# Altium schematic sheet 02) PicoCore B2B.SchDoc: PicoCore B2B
size A3; Origin: Eagle; DocumentNumber: 2; SheetNumber: 2; SheetTotal: 10
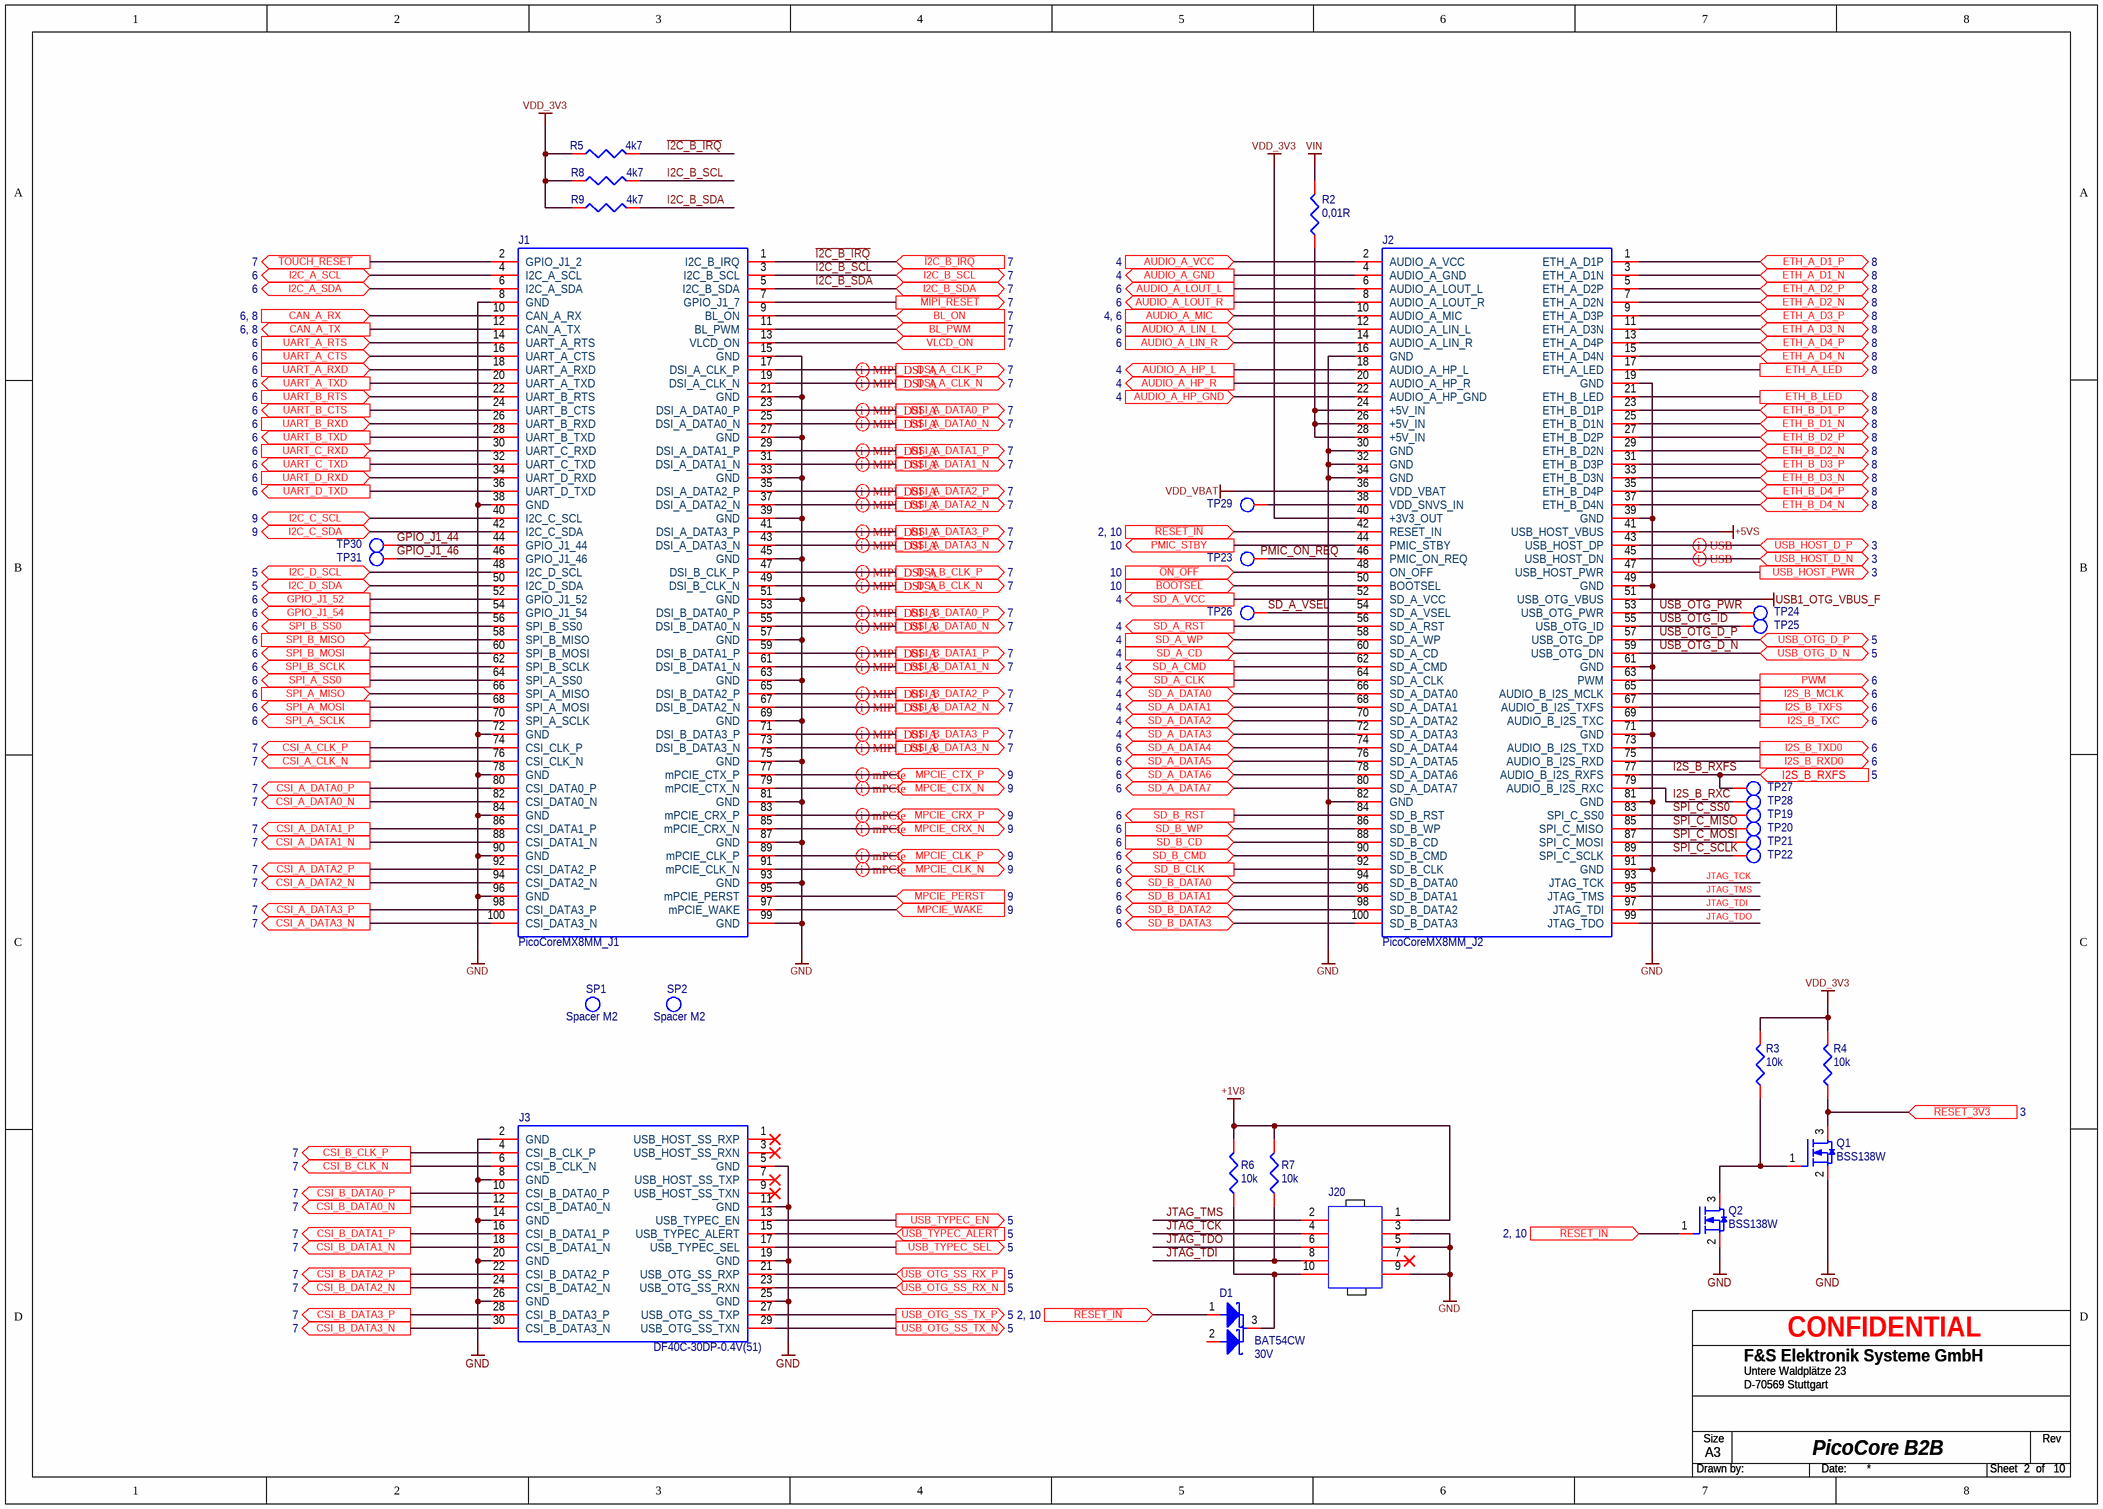
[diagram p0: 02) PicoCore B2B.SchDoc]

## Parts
D1  BAT54CW  Voltage: 30V  [SOT323 (SC70)]
J1  PicoCoreMX8MM_J1  [DF40C-100DS-0.4V(51)]
J2  PicoCoreMX8MM_J2  [DF40C-100DS-0.4V(51)]
J3  DF40C-30DP-0.4V(51)  [DF40C-30DS-0.4V(51)]
J20  (no value)  [J-B2B-5X2-127MM-WR-PHD]
Q1  BSS138W  [SOT323 (SC70)]
Q2  BSS138W  [SOT323 (SC70)]
R2  0,01R  [R0805]
R3  10k  [R0402]
R4  10k  [R0402]
R5  4k7  [R0402]
R6  10k  [R0402]
R7  10k  [R0402]
R8  4k7  [R0402]
R9  4k7  [R0402]
SP1  Spacer M2  [Spacer_M2]
SP2  Spacer M2  [Spacer_M2]
TP19  TESTPOINT  [TESTPOINT]  (value not drawn)  (mechanical)
TP20  TESTPOINT  [TESTPOINT]  (value not drawn)  (mechanical)
TP21  TESTPOINT  [TESTPOINT]  (value not drawn)  (mechanical)
TP22  TESTPOINT  [TESTPOINT]  (value not drawn)  (mechanical)
TP23  TESTPOINT  [TESTPOINT]  (value not drawn)  (mechanical)
TP24  TESTPOINT  [TESTPOINT]  (value not drawn)  (mechanical)
TP25  TESTPOINT  [TESTPOINT]  (value not drawn)  (mechanical)
TP26  TESTPOINT  [TESTPOINT]  (value not drawn)  (mechanical)
TP27  TESTPOINT  [TESTPOINT]  (value not drawn)  (mechanical)
TP28  TESTPOINT  [TESTPOINT]  (value not drawn)  (mechanical)
TP29  TESTPOINT  [TESTPOINT]  (value not drawn)  (mechanical)
TP30  TESTPOINT  [TESTPOINT]  (value not drawn)  (mechanical)
TP31  TESTPOINT  [TESTPOINT]  (value not drawn)  (mechanical)

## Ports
AUDIO_A_GND (out, see 4), AUDIO_A_HP_GND (in, see 4), AUDIO_A_HP_L (out, see 4), AUDIO_A_HP_R (out, see 4), AUDIO_A_LIN_L (in, see 6), AUDIO_A_LIN_R (in, see 6), AUDIO_A_LOUT_L (out, see 6), AUDIO_A_LOUT_R (out, see 6), AUDIO_A_MIC (in, see 4, 6), AUDIO_A_VCC (in, see 4), BL_ON (in, see 7), BL_PWM (in, see 7), CAN_A_RX (in, see 6, 8), CAN_A_TX (out, see 6, 8), CSI_A_CLK_N (out, see 7), CSI_A_CLK_P (out, see 7), CSI_A_DATA0_N (out, see 7), CSI_A_DATA0_P (out, see 7), CSI_A_DATA1_N (out, see 7), CSI_A_DATA1_P (out, see 7), CSI_A_DATA2_N (out, see 7), CSI_A_DATA2_P (out, see 7), CSI_A_DATA3_N (out, see 7), CSI_A_DATA3_P (out, see 7), CSI_B_CLK_N (out, see 7), CSI_B_CLK_P (out, see 7), CSI_B_DATA0_N (out, see 7), CSI_B_DATA0_P (out, see 7), CSI_B_DATA1_N (out, see 7), CSI_B_DATA1_P (out, see 7), CSI_B_DATA2_N (out, see 7), CSI_B_DATA2_P (out, see 7), CSI_B_DATA3_N (out, see 7), CSI_B_DATA3_P (out, see 7), DSI_A_CLK_N (out, see 7), DSI_A_CLK_P (out, see 7), DSI_A_DATA0_N (out, see 7), DSI_A_DATA0_P (out, see 7), DSI_A_DATA1_N (out, see 7), DSI_A_DATA1_P (out, see 7), DSI_A_DATA2_N (out, see 7), DSI_A_DATA2_P (out, see 7), DSI_A_DATA3_N (out, see 7), DSI_A_DATA3_P (out, see 7), DSI_B_CLK_N (out, see 7), DSI_B_CLK_P (out, see 7), DSI_B_DATA0_N (out, see 7), DSI_B_DATA0_P (out, see 7), DSI_B_DATA1_N (out, see 7), DSI_B_DATA1_P (out, see 7), DSI_B_DATA2_N (out, see 7), DSI_B_DATA2_P (out, see 7), DSI_B_DATA3_N (out, see 7), DSI_B_DATA3_P (out, see 7), ETH_A_D1_N (bidir, see 8), ETH_A_D1_P (bidir, see 8), ETH_A_D2_N (bidir, see 8), ETH_A_D2_P (bidir, see 8), ETH_A_D3_N (bidir, see 8), ETH_A_D3_P (bidir, see 8), ETH_A_D4_N (bidir, see 8), ETH_A_D4_P (bidir, see 8), ETH_A_LED (out, see 8), ETH_B_D1_N (bidir, see 8), ETH_B_D1_P (bidir, see 8), ETH_B_D2_N (bidir, see 8), ETH_B_D2_P (bidir, see 8), ETH_B_D3_N (bidir, see 8), ETH_B_D3_P (bidir, see 8), ETH_B_D4_N (bidir, see 8), ETH_B_D4_P (bidir, see 8), ETH_B_LED (out, see 8), GPIO_J1_52 (out, see 6), GPIO_J1_54 (out, see 6), I2C_A_SCL (bidir, see 6), I2C_A_SDA (bidir, see 6), I2C_B_SCL (bidir, see 7), I2C_B_SDA (bidir, see 7), I2C_C_SCL (bidir, see 9), I2C_C_SDA (bidir, see 9), I2C_D_SCL (bidir, see 5), I2C_D_SDA (bidir, see 5), I2S_B_MCLK (out, see 6), I2S_B_RXD0 (out, see 6), I2S_B_RXFS (in, see 5), I2S_B_TXC (out, see 6), I2S_B_TXD0 (out, see 6), I2S_B_TXFS (out, see 6), MPCIE_CLK_N (bidir, see 9), MPCIE_CLK_P (bidir, see 9), MPCIE_CRX_N (bidir, see 9), MPCIE_CRX_P (bidir, see 9), MPCIE_CTX_N (bidir, see 9), MPCIE_CTX_P (bidir, see 9), MPCIE_PERST (in, see 9), MPCIE_WAKE (in, see 9), PMIC_STBY (out, see 10), PWM (out, see 6), SD_A_CD (in, see 4), SD_A_CLK (out, see 4), SD_A_CMD (out, see 4), SD_A_DATA0 (bidir, see 4), SD_A_DATA1 (bidir, see 4), SD_A_DATA2 (bidir, see 4), SD_A_DATA3 (bidir, see 4), SD_A_DATA4 (bidir, see 6), SD_A_DATA5 (bidir, see 6), SD_A_DATA6 (bidir, see 6), SD_A_DATA7 (bidir, see 6), SD_A_RST (out, see 4), SD_A_VCC (out, see 4), SD_A_WP (in, see 4), SD_B_CD (in, see 6), SD_B_CLK (out, see 6), SD_B_CMD (bidir, see 6), SD_B_DATA0 (bidir, see 6), SD_B_DATA1 (bidir, see 6), SD_B_DATA2 (bidir, see 6), SD_B_DATA3 (bidir, see 6), SD_B_RST (out, see 6), SD_B_WP (in, see 6), SPI_A_MISO (in, see 6), SPI_A_MOSI (out, see 6), SPI_A_SCLK (out, see 6), SPI_A_SS0 (out, see 6), SPI_B_MISO (in, see 6), SPI_B_MOSI (out, see 6), SPI_B_SCLK (out, see 6), SPI_B_SS0 (out, see 6), UART_A_CTS (in, see 6), UART_A_RTS (in, see 6), UART_A_RXD (in, see 6), UART_A_TXD (out, see 6), UART_B_CTS (out, see 6), UART_B_RTS (in, see 6), UART_B_RXD (in, see 6), UART_B_TXD (out, see 6), UART_C_RXD (in, see 6), UART_C_TXD (out, see 6), UART_D_RXD (in, see 6), UART_D_TXD (out, see 6), USB_HOST_D_N (bidir, see 3), USB_HOST_D_P (bidir, see 3), USB_HOST_PWR (out, see 3), USB_OTG_D_N (bidir, see 5), USB_OTG_D_P (bidir, see 5), USB_OTG_SS_RX_N (in, see 5), USB_OTG_SS_RX_P (in, see 5), USB_OTG_SS_TX_N (out, see 5), USB_OTG_SS_TX_P (out, see 5), USB_TYPEC_EN (out, see 5), USB_TYPEC_SEL (out, see 5), VLCD_ON (in, see 7), ~{BOOTSEL} (in, see 10), ~{I2C_B_IRQ} (in, see 7), ~{MIPI_RESET} (out, see 7), ~{ON_OFF} (in, see 10), ~{RESET_3V3} (in, see 3), ~{RESET_IN} (in, see 2, 10), ~{TOUCH_RESET} (out, see 7), ~{USB_TYPEC_ALERT} (in, see 5)

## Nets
+1V8: J20.1 R6.2 R7.2
+5VS: J2.41(USB_HOST_VBUS)
GND: J1.8(GND) J1.15(GND) J1.21(GND) J1.27(GND) J1.33(GND) J1.38(GND) J1.39(GND) J1.45(GND) J1.51(GND) J1.57(GND) J1.63(GND) J1.69(GND) J1.72(GND) J1.75(GND) J1.78(GND) J1.81(GND) J1.84(GND) J1.87(GND) J1.90(GND) J1.93(GND) J1.96(GND) J1.99(GND) J2.16(GND) J2.19(GND) J2.30(GND) J2.32(GND) J2.34(GND) J2.39(GND) J2.49(GND) J2.61(GND) J2.71(GND) J2.81(GND) J2.82(GND) J2.91(GND) J3.2(GND) J3.5(GND) J3.8(GND) J3.11(GND) J3.14(GND) J3.19(GND) J3.20(GND) J3.25(GND) J3.26(GND) J20.3 J20.5 J20.9 Q1.2 Q2.2
USB1_OTG_VBUS_F: J2.51(USB_OTG_VBUS)
VDD_3V3: J2.40(+3V3_OUT) R3.2 R4.2 R5.1 R8.1 R9.1
VDD_VBAT: J2.36(VDD_VBAT)
VIN: R2.2
~{RESET_3V3}: Q1.3 R4.1 ; port ~{RESET_3V3}
~{TOUCH_RESET}: J1.2(GPIO_J1_2) ; port ~{TOUCH_RESET}
~{USB_OTG_ID}: J2.55(USB_OTG_ID) TP25.1(TP)
~{USB_OTG_PWR}: J2.53(USB_OTG_PWR) TP24.1(TP)
~{USB_TYPEC_ALERT}: J3.15(USB_TYPEC_ALERT) ; port ~{USB_TYPEC_ALERT}
AUDIO_A_GND: J2.4(AUDIO_A_GND) ; port AUDIO_A_GND
AUDIO_A_HP_GND: J2.22(AUDIO_A_HP_GND) ; port AUDIO_A_HP_GND
AUDIO_A_HP_L: J2.18(AUDIO_A_HP_L) ; port AUDIO_A_HP_L
AUDIO_A_HP_R: J2.20(AUDIO_A_HP_R) ; port AUDIO_A_HP_R
AUDIO_A_LIN_L: J2.12(AUDIO_A_LIN_L) ; port AUDIO_A_LIN_L
AUDIO_A_LIN_R: J2.14(AUDIO_A_LIN_R) ; port AUDIO_A_LIN_R
AUDIO_A_LOUT_L: J2.6(AUDIO_A_LOUT_L) ; port AUDIO_A_LOUT_L
AUDIO_A_LOUT_R: J2.8(AUDIO_A_LOUT_R) ; port AUDIO_A_LOUT_R
AUDIO_A_MIC: J2.10(AUDIO_A_MIC) ; port AUDIO_A_MIC
AUDIO_A_VCC: J2.2(AUDIO_A_VCC) ; port AUDIO_A_VCC
~{BOOTSEL}: J2.50(BOOTSEL) ; port ~{BOOTSEL}
BL_ON: J1.9(BL_ON) ; port BL_ON
BL_PWM: J1.11(BL_PWM) ; port BL_PWM
CAN_A_RX: J1.10(CAN_A_RX) ; port CAN_A_RX
CAN_A_TX: J1.12(CAN_A_TX) ; port CAN_A_TX
CSI_A_CLK_N: J1.76(CSI_CLK_N) ; port CSI_A_CLK_N
CSI_A_CLK_P: J1.74(CSI_CLK_P) ; port CSI_A_CLK_P
CSI_A_DATA0_N: J1.82(CSI_DATA0_N) ; port CSI_A_DATA0_N
CSI_A_DATA0_P: J1.80(CSI_DATA0_P) ; port CSI_A_DATA0_P
CSI_A_DATA1_N: J1.88(CSI_DATA1_N) ; port CSI_A_DATA1_N
CSI_A_DATA1_P: J1.86(CSI_DATA1_P) ; port CSI_A_DATA1_P
CSI_A_DATA2_N: J1.94(CSI_DATA2_N) ; port CSI_A_DATA2_N
CSI_A_DATA2_P: J1.92(CSI_DATA2_P) ; port CSI_A_DATA2_P
CSI_A_DATA3_N: J1.100(CSI_DATA3_N) ; port CSI_A_DATA3_N
CSI_A_DATA3_P: J1.98(CSI_DATA3_P) ; port CSI_A_DATA3_P
CSI_B_CLK_N: J3.6(CSI_B_CLK_N) ; port CSI_B_CLK_N
CSI_B_CLK_P: J3.4(CSI_B_CLK_P) ; port CSI_B_CLK_P
CSI_B_DATA0_N: J3.12(CSI_B_DATA0_N) ; port CSI_B_DATA0_N
CSI_B_DATA0_P: J3.10(CSI_B_DATA0_P) ; port CSI_B_DATA0_P
CSI_B_DATA1_N: J3.18(CSI_B_DATA1_N) ; port CSI_B_DATA1_N
CSI_B_DATA1_P: J3.16(CSI_B_DATA1_P) ; port CSI_B_DATA1_P
CSI_B_DATA2_N: J3.24(CSI_B_DATA2_N) ; port CSI_B_DATA2_N
CSI_B_DATA2_P: J3.22(CSI_B_DATA2_P) ; port CSI_B_DATA2_P
CSI_B_DATA3_N: J3.30(CSI_B_DATA3_N) ; port CSI_B_DATA3_N
CSI_B_DATA3_P: J3.28(CSI_B_DATA3_P) ; port CSI_B_DATA3_P
DSI_A_CLK_N: J1.19(DSI_A_CLK_N) ; port DSI_A_CLK_N
DSI_A_CLK_P: J1.17(DSI_A_CLK_P) ; port DSI_A_CLK_P
DSI_A_DATA0_N: J1.25(DSI_A_DATA0_N) ; port DSI_A_DATA0_N
DSI_A_DATA0_P: J1.23(DSI_A_DATA0_P) ; port DSI_A_DATA0_P
DSI_A_DATA1_N: J1.31(DSI_A_DATA1_N) ; port DSI_A_DATA1_N
DSI_A_DATA1_P: J1.29(DSI_A_DATA1_P) ; port DSI_A_DATA1_P
DSI_A_DATA2_N: J1.37(DSI_A_DATA2_N) ; port DSI_A_DATA2_N
DSI_A_DATA2_P: J1.35(DSI_A_DATA2_P) ; port DSI_A_DATA2_P
DSI_A_DATA3_N: J1.43(DSI_A_DATA3_N) ; port DSI_A_DATA3_N
DSI_A_DATA3_P: J1.41(DSI_A_DATA3_P) ; port DSI_A_DATA3_P
DSI_B_CLK_N: J1.49(DSI_B_CLK_N) ; port DSI_B_CLK_N
DSI_B_CLK_P: J1.47(DSI_B_CLK_P) ; port DSI_B_CLK_P
DSI_B_DATA0_N: J1.55(DSI_B_DATA0_N) ; port DSI_B_DATA0_N
DSI_B_DATA0_P: J1.53(DSI_B_DATA0_P) ; port DSI_B_DATA0_P
DSI_B_DATA1_N: J1.61(DSI_B_DATA1_N) ; port DSI_B_DATA1_N
DSI_B_DATA1_P: J1.59(DSI_B_DATA1_P) ; port DSI_B_DATA1_P
DSI_B_DATA2_N: J1.67(DSI_B_DATA2_N) ; port DSI_B_DATA2_N
DSI_B_DATA2_P: J1.65(DSI_B_DATA2_P) ; port DSI_B_DATA2_P
DSI_B_DATA3_N: J1.73(DSI_B_DATA3_N) ; port DSI_B_DATA3_N
DSI_B_DATA3_P: J1.71(DSI_B_DATA3_P) ; port DSI_B_DATA3_P
ETH_A_D1_N: J2.3(ETH_A_D1N) ; port ETH_A_D1_N
ETH_A_D1_P: J2.1(ETH_A_D1P) ; port ETH_A_D1_P
ETH_A_D2_N: J2.7(ETH_A_D2N) ; port ETH_A_D2_N
ETH_A_D2_P: J2.5(ETH_A_D2P) ; port ETH_A_D2_P
ETH_A_D3_N: J2.11(ETH_A_D3N) ; port ETH_A_D3_N
ETH_A_D3_P: J2.9(ETH_A_D3P) ; port ETH_A_D3_P
ETH_A_D4_N: J2.15(ETH_A_D4N) ; port ETH_A_D4_N
ETH_A_D4_P: J2.13(ETH_A_D4P) ; port ETH_A_D4_P
ETH_A_LED: J2.17(ETH_A_LED) ; port ETH_A_LED
ETH_B_D1_N: J2.25(ETH_B_D1N) ; port ETH_B_D1_N
ETH_B_D1_P: J2.23(ETH_B_D1P) ; port ETH_B_D1_P
ETH_B_D2_N: J2.29(ETH_B_D2N) ; port ETH_B_D2_N
ETH_B_D2_P: J2.27(ETH_B_D2P) ; port ETH_B_D2_P
ETH_B_D3_N: J2.33(ETH_B_D3N) ; port ETH_B_D3_N
ETH_B_D3_P: J2.31(ETH_B_D3P) ; port ETH_B_D3_P
ETH_B_D4_N: J2.37(ETH_B_D4N) ; port ETH_B_D4_N
ETH_B_D4_P: J2.35(ETH_B_D4P) ; port ETH_B_D4_P
ETH_B_LED: J2.21(ETH_B_LED) ; port ETH_B_LED
GPIO_J1_44: J1.44(GPIO_J1_44) TP30.1(TP)
GPIO_J1_46: J1.46(GPIO_J1_46) TP31.1(TP)
GPIO_J1_52: J1.52(GPIO_J1_52) ; port GPIO_J1_52
GPIO_J1_54: J1.54(GPIO_J1_54) ; port GPIO_J1_54
I2C_A_SCL: J1.4(I2C_A_SCL) ; port I2C_A_SCL
I2C_A_SDA: J1.6(I2C_A_SDA) ; port I2C_A_SDA
I2C_B_SCL: J1.3(I2C_B_SCL) R8.2 ; port I2C_B_SCL
I2C_B_SDA: J1.5(I2C_B_SDA) R9.2 ; port I2C_B_SDA
I2C_C_SCL: J1.40(I2C_C_SCL) ; port I2C_C_SCL
I2C_C_SDA: J1.42(I2C_C_SDA) ; port I2C_C_SDA
I2C_D_SCL: J1.48(I2C_D_SCL) ; port I2C_D_SCL
I2C_D_SDA: J1.50(I2C_D_SDA) ; port I2C_D_SDA
I2S_B_MCLK: J2.65(AUDIO_B_I2S_MCLK) ; port I2S_B_MCLK
I2S_B_RXC: J2.79(AUDIO_B_I2S_RXC) TP28.1(TP)
I2S_B_RXD0: J2.75(AUDIO_B_I2S_RXD) ; port I2S_B_RXD0
I2S_B_RXFS: J2.77(AUDIO_B_I2S_RXFS) TP27.1(TP) ; port I2S_B_RXFS
I2S_B_TXC: J2.69(AUDIO_B_I2S_TXC) ; port I2S_B_TXC
I2S_B_TXD0: J2.73(AUDIO_B_I2S_TXD) ; port I2S_B_TXD0
I2S_B_TXFS: J2.67(AUDIO_B_I2S_TXFS) ; port I2S_B_TXFS
~{I2C_B_IRQ}: J1.1(I2C_B_IRQ) R5.2 ; port ~{I2C_B_IRQ}
JTAG_TCK: J2.93(JTAG_TCK) J20.4
JTAG_TDI: J2.97(JTAG_TDI) J20.8 R7.1
JTAG_TDO: J2.99(JTAG_TDO) J20.6
JTAG_TMS: J2.95(JTAG_TMS) J20.2
~{MIPI_RESET}: J1.7(GPIO_J1_7) ; port ~{MIPI_RESET}
MPCIE_CLK_N: J1.91(mPCIE_CLK_N) ; port MPCIE_CLK_N
MPCIE_CLK_P: J1.89(mPCIE_CLK_P) ; port MPCIE_CLK_P
MPCIE_CRX_N: J1.85(mPCIE_CRX_N) ; port MPCIE_CRX_N
MPCIE_CRX_P: J1.83(mPCIE_CRX_P) ; port MPCIE_CRX_P
MPCIE_CTX_N: J1.79(mPCIE_CTX_N) ; port MPCIE_CTX_N
MPCIE_CTX_P: J1.77(mPCIE_CTX_P) ; port MPCIE_CTX_P
MPCIE_PERST: J1.95(mPCIE_PERST) ; port MPCIE_PERST
MPCIE_WAKE: J1.97(mPCIE_WAKE) ; port MPCIE_WAKE
~{ON_OFF}: J2.48(ON_OFF) ; port ~{ON_OFF}
PMIC_STBY: J2.44(PMIC_STBY) ; port PMIC_STBY
PWM: J2.63(PWM) ; port PWM
~{RESET_IN}: D1.1(ANODE1) J2.42(RESET_IN) Q2.1 ; port ~{RESET_IN}
SD_A_CD: J2.60(SD_A_CD) ; port SD_A_CD
SD_A_CLK: J2.64(SD_A_CLK) ; port SD_A_CLK
SD_A_CMD: J2.62(SD_A_CMD) ; port SD_A_CMD
SD_A_DATA0: J2.66(SD_A_DATA0) ; port SD_A_DATA0
SD_A_DATA1: J2.68(SD_A_DATA1) ; port SD_A_DATA1
SD_A_DATA2: J2.70(SD_A_DATA2) ; port SD_A_DATA2
SD_A_DATA3: J2.72(SD_A_DATA3) ; port SD_A_DATA3
SD_A_DATA4: J2.74(SD_A_DATA4) ; port SD_A_DATA4
SD_A_DATA5: J2.76(SD_A_DATA5) ; port SD_A_DATA5
SD_A_DATA6: J2.78(SD_A_DATA6) ; port SD_A_DATA6
SD_A_DATA7: J2.80(SD_A_DATA7) ; port SD_A_DATA7
SD_A_RST: J2.56(SD_A_RST) ; port SD_A_RST
SD_A_VCC: J2.52(SD_A_VCC) ; port SD_A_VCC
SD_A_VSEL: J2.54(SD_A_VSEL) TP26.1(TP)
SD_A_WP: J2.58(SD_A_WP) ; port SD_A_WP
SD_B_CD: J2.88(SD_B_CD) ; port SD_B_CD
SD_B_CLK: J2.92(SD_B_CLK) ; port SD_B_CLK
SD_B_CMD: J2.90(SD_B_CMD) ; port SD_B_CMD
SD_B_DATA0: J2.94(SD_B_DATA0) ; port SD_B_DATA0
SD_B_DATA1: J2.96(SD_B_DATA1) ; port SD_B_DATA1
SD_B_DATA2: J2.98(SD_B_DATA2) ; port SD_B_DATA2
SD_B_DATA3: J2.100(SD_B_DATA3) ; port SD_B_DATA3
SD_B_RST: J2.84(SD_B_RST) ; port SD_B_RST
SD_B_WP: J2.86(SD_B_WP) ; port SD_B_WP
SPI_A_MISO: J1.66(SPI_A_MISO) ; port SPI_A_MISO
SPI_A_MOSI: J1.68(SPI_A_MOSI) ; port SPI_A_MOSI
SPI_A_SCLK: J1.70(SPI_A_SCLK) ; port SPI_A_SCLK
SPI_A_SS0: J1.64(SPI_A_SS0) ; port SPI_A_SS0
SPI_B_MISO: J1.58(SPI_B_MISO) ; port SPI_B_MISO
SPI_B_MOSI: J1.60(SPI_B_MOSI) ; port SPI_B_MOSI
SPI_B_SCLK: J1.62(SPI_B_SCLK) ; port SPI_B_SCLK
SPI_B_SS0: J1.56(SPI_B_SS0) ; port SPI_B_SS0
SPI_C_MISO: J2.85(SPI_C_MISO) TP20.1(TP)
SPI_C_MOSI: J2.87(SPI_C_MOSI) TP21.1(TP)
SPI_C_SCLK: J2.89(SPI_C_SCLK) TP22.1(TP)
SPI_C_SS0: J2.83(SPI_C_SS0) TP19.1(TP)
UART_A_CTS: J1.16(UART_A_CTS) ; port UART_A_CTS
UART_A_RTS: J1.14(UART_A_RTS) ; port UART_A_RTS
UART_A_RXD: J1.18(UART_A_RXD) ; port UART_A_RXD
UART_A_TXD: J1.20(UART_A_TXD) ; port UART_A_TXD
UART_B_CTS: J1.24(UART_B_CTS) ; port UART_B_CTS
UART_B_RTS: J1.22(UART_B_RTS) ; port UART_B_RTS
UART_B_RXD: J1.26(UART_B_RXD) ; port UART_B_RXD
UART_B_TXD: J1.28(UART_B_TXD) ; port UART_B_TXD
UART_C_RXD: J1.30(UART_C_RXD) ; port UART_C_RXD
UART_C_TXD: J1.32(UART_C_TXD) ; port UART_C_TXD
UART_D_RXD: J1.34(UART_D_RXD) ; port UART_D_RXD
UART_D_TXD: J1.36(UART_D_TXD) ; port UART_D_TXD
USB_HOST_D_N: J2.45(USB_HOST_DN) ; port USB_HOST_D_N
USB_HOST_D_P: J2.43(USB_HOST_DP) ; port USB_HOST_D_P
USB_HOST_PWR: J2.47(USB_HOST_PWR) ; port USB_HOST_PWR
USB_OTG_D_N: J2.59(USB_OTG_DN) ; port USB_OTG_D_N
USB_OTG_D_P: J2.57(USB_OTG_DP) ; port USB_OTG_D_P
USB_OTG_SS_RX_N: J3.23(USB_OTG_SS_RXN) ; port USB_OTG_SS_RX_N
USB_OTG_SS_RX_P: J3.21(USB_OTG_SS_RXP) ; port USB_OTG_SS_RX_P
USB_OTG_SS_TX_N: J3.29(USB_OTG_SS_TXN) ; port USB_OTG_SS_TX_N
USB_OTG_SS_TX_P: J3.27(USB_OTG_SS_TXP) ; port USB_OTG_SS_TX_P
USB_TYPEC_EN: J3.13(USB_TYPEC_EN) ; port USB_TYPEC_EN
USB_TYPEC_SEL: J3.17(USB_TYPEC_SEL) ; port USB_TYPEC_SEL
VLCD_ON: J1.13(VLCD_ON) ; port VLCD_ON
NetD1_3: D1.3(CATHODE) J20.10 R6.1
NetJ2_24: J2.24(+5V_IN) J2.26(+5V_IN) J2.28(+5V_IN) R2.1
NetJ2_38: J2.38(VDD_SNVS_IN) TP29.1(TP)
NetJ2_46: J2.46(PMIC_ON_REQ) TP23.1(TP)
NetQ1_1: Q1.1 Q2.3 R3.1

Not connected (* = marked no-connect by the designer): D1 2(ANODE2); J3 1(USB_HOST_SS_RXP)* 3(USB_HOST_SS_RXN)* 7(USB_HOST_SS_TXP)* 9(USB_HOST_SS_TXN)*; J20 7*

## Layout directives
differential pair; differential pair class mPCIe: MPCIE_CLK_N, MPCIE_CLK_P, MPCIE_CRX_N, MPCIE_CRX_P, MPCIE_CTX_N, MPCIE_CTX_P
differential pair; differential pair class MIPI-DSI_A: DSI_A_CLK_N, DSI_A_CLK_P, DSI_A_DATA0_N, DSI_A_DATA0_P, DSI_A_DATA1_N, DSI_A_DATA1_P, DSI_A_DATA2_N, DSI_A_DATA2_P, DSI_A_DATA3_N, DSI_A_DATA3_P, DSI_B_CLK_N, DSI_B_CLK_P, DSI_B_DATA0_N, DSI_B_DATA0_P, DSI_B_DATA1_N, DSI_B_DATA1_P, DSI_B_DATA2_N, DSI_B_DATA2_P, DSI_B_DATA3_N, DSI_B_DATA3_P
differential pair; differential pair class USB: USB_HOST_D_N, USB_HOST_D_P

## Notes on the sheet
- Labels drawn without touching a wire or pin: PMIC_ON_REQ

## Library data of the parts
D1 = 2695: BAT54CW  30V  200mA  Dual Common Cathode SOT-323; FS-EDV-Nummer: B.DSCHOT.5; Class: DIOD; ID: 2695
J1 = PicoCoreMX8MM_J1: FS-EDV-Nummer: B.MBU.2R100PS.3
J2 = PicoCoreMX8MM_J2: FS-EDV-Nummer: B.MBU.2R100PS.3
J3 = 2764: 30 pol. 2 reih. Steckerl. SMD RM0,4; ID: 2764; Class: Connector; FS-EDV-Nummer: B.MBU.2R30PS.1
J20 = 2706: Stiftl. 10 pol. 2 reih. SMD RM:1,27; Part Number: M50-3610542; FS-EDV-Nummer: B.MST.2R10PS.14; Class: Connector; ID: 2706
Q1 Q2 = 2689: BSS138W SOT323(SC-70) N-Kanal; FS-EDV-Nummer: B.TPMFN.10; Class: MOSFET; ID: 2689
R2 = 187: 0,01R 1/4W max 5% SMD 0805; FS-EDV-Nummer: B.R0R01.1; Tolerance: 5; ID: 187
R3 R4 R6 R7 = 170: 10k 1/16W 1% SMD 0402; FS-EDV-Nummer: B.R10K.3; Tolerance: 1; ID: 170
R5 R8 R9 = 184: 4k7 1/16W max 5% SMD 0402; FS-EDV-Nummer: B.R4K7.3; Tolerance: 5; ID: 184
SP1 SP2 = 2747: SMD-Distanzbolzen 1.5mm M2; Part Number: 9774015243R; ID: 2747; Class: Mechanical; FS-EDV-Nummer: B.MSCHR.22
